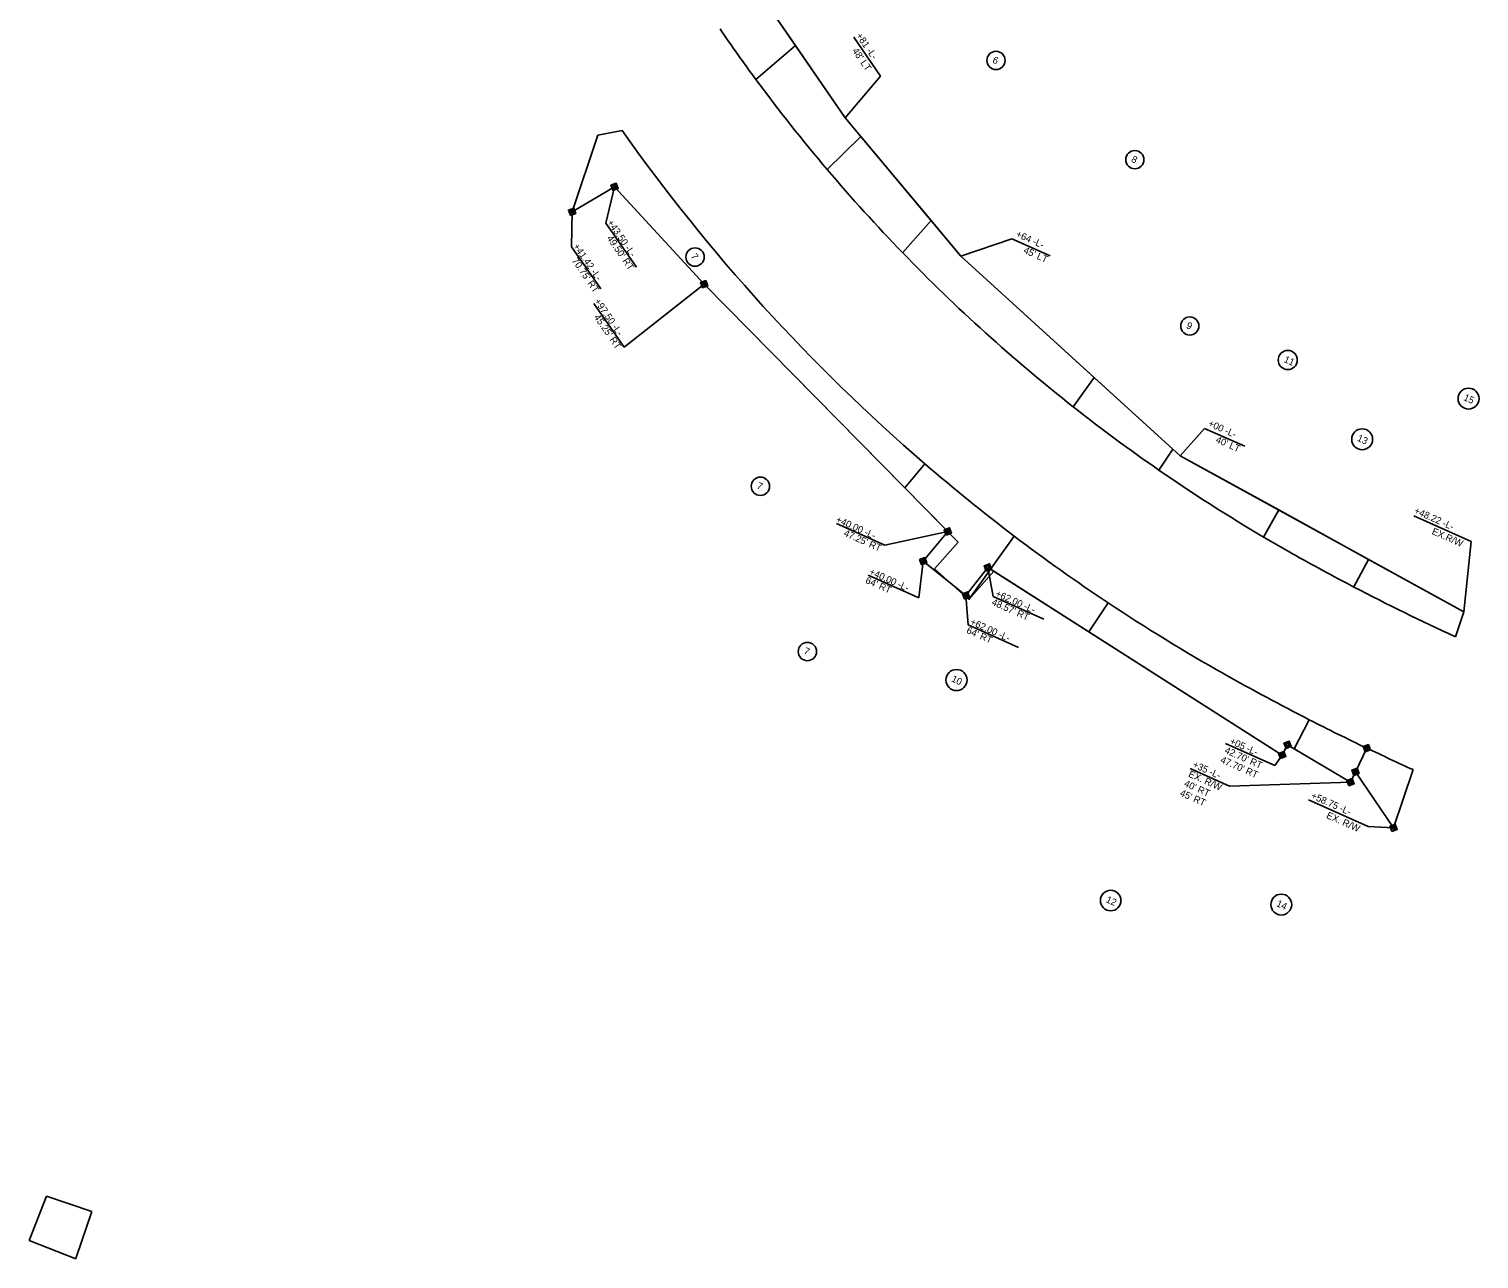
# Model space of a CAD drawing. Extents: x 2298011 to 2299093, y 599361 to 600353.
# Drawn here: x 2298011 to 2298640, y 599406 to 599940 of the extents above; entities that cross this region are included whole.
import ezdxf

# ---------------------------------------------------------------- set-up
doc = ezdxf.new("R2010")
doc.units = 0
for name, color, linetype in [('Prop Easement Construction', 7, 'Continuous'), ('Prop Easement Construction Station Offsets', 7, 'Continuous'), ('Prop Easement Permanent Drainage', 7, 'Continuous'), ('Prop Easement Permanent Drainage Station Offsets', 7, 'Continuous'), ('Prop Easement Permanent Utility', 7, 'Continuous'), ('Prop Easement Permanent Utility Station Offsets', 7, 'Continuous'), ('Prop Parcel Number Text', 7, 'Continuous'), ('Prop ROW Marker CELL', 7, 'Continuous'), ('Prop ROW Permanent Easement CELL', 7, 'Continuous'), ('Scratch_Level_2', 7, 'Continuous'), ('Scratch_Level_4', 7, 'Continuous'), ('Scratch_Level_5', 7, 'Continuous'), ('Scratch_Level_6', 7, 'Continuous')]:
    doc.layers.add(name, color=color, linetype=linetype)

msp = doc.modelspace()

# ---------------------------------------------------------------- linework, layer by layer
at = {"layer": 'Prop Easement Construction'}
for p, q in [((2298319.51, 599967.44), (2298365.22, 599901.13)), ((2298365.22, 599901.13), (2298415.34, 599841.11)), ((2298415.34, 599841.11), (2298510.52, 599754.45)), ((2298510.52, 599754.45), (2298633.57, 599686.89))]:
    msp.add_line(p, q, dxfattribs=at)
at = {"layer": 'Prop Easement Construction Station Offsets'}
for p, q in [((2298380.55, 599919.15), (2298368.88, 599936.09)), ((2298454.03, 599841.2), (2298437.51, 599848.57)), ((2298538.45, 599758.63), (2298521.09, 599766.38)), ((2298636.74, 599717.38), (2298611.76, 599728.53))]:
    msp.add_line(p, q, dxfattribs=at)
for points in [[(2298380.55, 599919.15), (2298365.22, 599901.13)], [(2298437.51, 599848.57), (2298415.34, 599841.11)], [(2298521.09, 599766.38), (2298510.52, 599754.45)], [(2298636.74, 599717.38), (2298633.57, 599686.89)]]:
    msp.add_lwpolyline(points, dxfattribs=at)
at = {"layer": 'Prop Easement Permanent Drainage'}
for q in [(2298591.42, 599627.76), (2298603.03, 599593.21)]:
    msp.add_line((2298586.49, 599617.47), q, dxfattribs=at)
at = {"layer": 'Prop Easement Permanent Drainage Station Offsets'}
for p, q in [((2298531.8, 599611.31), (2298514.83, 599618.89)), ((2298592.08, 599593.74), (2298566.18, 599605.3))]:
    msp.add_line(p, q, dxfattribs=at)
for points in [[(2298584.34, 599612.96), (2298531.8, 599611.31)], [(2298603.03, 599593.21), (2298592.08, 599593.74)]]:
    msp.add_lwpolyline(points, dxfattribs=at)
at = {"layer": 'Prop Easement Permanent Utility'}
for p, q in [((2298246.73, 599860.36), (2298265.17, 599871.14)), ((2298265.17, 599871.14), (2298303.97, 599828.92)), ((2298303.97, 599828.92), (2298409.7, 599721.74)), ((2298409.7, 599721.74), (2298399.05, 599708.83)), ((2298399.05, 599708.83), (2298417.58, 599693.96)), ((2298417.58, 599693.96), (2298427.07, 599706.13)), ((2298427.07, 599706.13), (2298554.76, 599624.77)), ((2298554.76, 599624.77), (2298557.08, 599629.2)), ((2298557.08, 599629.2), (2298584.34, 599612.96)), ((2298584.34, 599612.96), (2298586.49, 599617.47))]:
    msp.add_line(p, q, dxfattribs=at)
at = {"layer": 'Prop Easement Permanent Utility Station Offsets'}
for p, q in [((2298274.63, 599836.25), (2298261.41, 599855.45)), ((2298259.13, 599826.9), (2298246.54, 599845.19)), ((2298269.26, 599801.68), (2298256.21, 599820.62)), ((2298382.35, 599715.8), (2298361.35, 599725.17)), ((2298397.06, 599693), (2298375.14, 599702.78)), ((2298451.31, 599683.66), (2298429.39, 599693.44)), ((2298440.38, 599671.4), (2298418.46, 599681.18)), ((2298551.58, 599620.2), (2298530.09, 599629.79))]:
    msp.add_line(p, q, dxfattribs=at)
for points in [[(2298265.17, 599871.14), (2298261.41, 599855.45)], [(2298246.73, 599860.36), (2298246.54, 599845.19)], [(2298303.97, 599828.92), (2298269.26, 599801.68)], [(2298382.35, 599715.8), (2298409.7, 599721.74)], [(2298397.06, 599693), (2298399.05, 599708.83)], [(2298427.07, 599706.13), (2298429.39, 599693.44)], [(2298417.58, 599693.96), (2298418.46, 599681.18)], [(2298554.76, 599624.77), (2298551.58, 599620.2)]]:
    msp.add_lwpolyline(points, dxfattribs=at)
at = {"layer": 'Prop Parcel Number Text'}
for centre, radius in [((2298430.58, 599925.96), 3.95), ((2298490.8, 599882.94), 3.95), ((2298300.07, 599840.71), 3.98), ((2298514.64, 599810.81), 3.94), ((2298557.14, 599796.05), 4.15), ((2298635.55, 599779.31), 4.54), ((2298589.4, 599761.68), 4.53), ((2298328.43, 599741.29), 3.98), ((2298348.79, 599669.65), 3.98), ((2298413.47, 599657.29), 4.58), ((2298480.35, 599561.66), 4.46), ((2298554.33, 599559.91), 4.52)]:
    msp.add_circle(centre, radius, dxfattribs=at)
at = {"layer": 'Prop ROW Marker CELL'}
for p, q in [((2298265.17, 599871.14), (2298265.17, 599871.14)), ((2298246.73, 599860.36), (2298246.73, 599860.36)), ((2298303.97, 599828.92), (2298303.97, 599828.92)), ((2298409.7, 599721.74), (2298409.7, 599721.74)), ((2298399.05, 599708.83), (2298399.05, 599708.83)), ((2298427.07, 599706.13), (2298427.07, 599706.13)), ((2298417.58, 599693.96), (2298417.58, 599693.96)), ((2298557.08, 599629.2), (2298557.08, 599629.2)), ((2298554.76, 599624.77), (2298554.76, 599624.77)), ((2298591.42, 599627.76), (2298591.42, 599627.76)), ((2298586.49, 599617.47), (2298586.49, 599617.47)), ((2298584.34, 599612.96), (2298584.34, 599612.96)), ((2298603.03, 599593.21), (2298603.03, 599593.21))]:
    msp.add_line(p, q, dxfattribs=at)
at = {"layer": 'Prop ROW Permanent Easement CELL'}
for points in [[(2298264.47, 599869.57), (2298263.59, 599871.85), (2298265.88, 599872.72), (2298266.75, 599870.44)], [(2298264.82, 599870.35), (2298264.38, 599871.5), (2298265.52, 599871.93), (2298265.96, 599870.79)], [(2298246.02, 599858.78), (2298245.15, 599861.06), (2298247.43, 599861.94), (2298248.3, 599859.65)], [(2298246.37, 599859.57), (2298245.94, 599860.71), (2298247.08, 599861.15), (2298247.51, 599860.01)], [(2298303.27, 599827.34), (2298302.39, 599829.62), (2298304.68, 599830.5), (2298305.55, 599828.22)], [(2298303.62, 599828.13), (2298303.18, 599829.27), (2298304.32, 599829.71), (2298304.76, 599828.57)], [(2298409, 599720.16), (2298408.13, 599722.45), (2298410.41, 599723.32), (2298411.28, 599721.04)], [(2298409.35, 599720.95), (2298408.91, 599722.09), (2298410.06, 599722.53), (2298410.49, 599721.39)], [(2298398.34, 599707.25), (2298397.47, 599709.53), (2298399.75, 599710.4), (2298400.62, 599708.12)], [(2298398.69, 599708.04), (2298398.26, 599709.18), (2298399.4, 599709.61), (2298399.83, 599708.47)], [(2298426.36, 599704.55), (2298425.49, 599706.83), (2298427.77, 599707.7), (2298428.65, 599705.42)], [(2298426.72, 599705.34), (2298426.28, 599706.48), (2298427.42, 599706.91), (2298427.86, 599705.77)], [(2298416.87, 599692.38), (2298416, 599694.66), (2298418.28, 599695.54), (2298419.16, 599693.25)], [(2298417.23, 599693.17), (2298416.79, 599694.31), (2298417.93, 599694.75), (2298418.37, 599693.61)], [(2298556.38, 599627.62), (2298555.5, 599629.9), (2298557.79, 599630.77), (2298558.66, 599628.49)], [(2298556.73, 599628.41), (2298556.29, 599629.55), (2298557.43, 599629.99), (2298557.87, 599628.84)], [(2298590.71, 599626.18), (2298589.84, 599628.46), (2298592.12, 599629.33), (2298592.99, 599627.05)], [(2298554.05, 599623.19), (2298553.18, 599625.47), (2298555.46, 599626.35), (2298556.34, 599624.07)], [(2298554.41, 599623.98), (2298553.97, 599625.12), (2298555.11, 599625.56), (2298555.55, 599624.42)], [(2298591.06, 599626.97), (2298590.63, 599628.11), (2298591.77, 599628.55), (2298592.2, 599627.4)], [(2298585.79, 599615.89), (2298584.92, 599618.17), (2298587.2, 599619.04), (2298588.07, 599616.76)], [(2298586.14, 599616.68), (2298585.7, 599617.82), (2298586.85, 599618.25), (2298587.28, 599617.11)], [(2298583.63, 599611.38), (2298582.76, 599613.66), (2298585.04, 599614.53), (2298585.91, 599612.25)], [(2298583.98, 599612.17), (2298583.55, 599613.31), (2298584.69, 599613.74), (2298585.13, 599612.6)], [(2298602.33, 599591.63), (2298601.45, 599593.91), (2298603.73, 599594.79), (2298604.61, 599592.5)], [(2298602.68, 599592.42), (2298602.24, 599593.56), (2298603.38, 599594), (2298603.82, 599592.86)]]:
    msp.add_lwpolyline(points, close=True, dxfattribs=at)
at = {"layer": 'Scratch_Level_2'}
for p, q in [((2298591.42, 599627.76), (2298586.5, 599617.48)), ((2298586.5, 599617.48), (2298603.03, 599593.21)), ((2298603.03, 599593.21), (2298611.51, 599618.43)), ((2298018.76, 599433.52), (2298011.18, 599414.21)), ((2298038.38, 599426.89), (2298018.76, 599433.52)), ((2298031.7, 599406.93), (2298038.38, 599426.89)), ((2298011.18, 599414.21), (2298031.47, 599406.24)), ((2298031.47, 599406.24), (2298031.7, 599406.93))]:
    msp.add_line(p, q, dxfattribs=at)
msp.add_arc((2299031.95, 600551.04), 1023, 244.4927, 245.73365, dxfattribs=at)
at = {"layer": 'Scratch_Level_4'}
for p, q in [((2298257.83, 599893.53), (2298246.73, 599860.36)), ((2298268.41, 599895.58), (2298257.83, 599893.53)), ((2298246.73, 599860.36), (2298265.17, 599871.14)), ((2298265.17, 599871.14), (2298265.17, 599871.14)), ((2298399.69, 599751.09), (2298391.09, 599740.61)), ((2298391.09, 599740.61), (2298399.69, 599751.09)), ((2298391.09, 599740.61), (2298414.25, 599717.13)), ((2298414.25, 599717.13), (2298403.87, 599705.48)), ((2298418.8, 599692.17), (2298438.5, 599719.7)), ((2298438.5, 599719.7), (2298418.8, 599692.17)), ((2298403.87, 599705.48), (2298418.8, 599692.17)), ((2298418.8, 599692.17), (2298429.72, 599704.43)), ((2298429.72, 599704.43), (2298429.72, 599704.43)), ((2298429.72, 599704.43), (2298470.92, 599678.19)), ((2298470.92, 599678.19), (2298479.26, 599690.73)), ((2298479.26, 599690.73), (2298470.92, 599678.19)), ((2298470.92, 599678.19), (2298554.76, 599624.77)), ((2298529.29, 599660.05), (2298529.46, 599659.96)), ((2298529.46, 599659.96), (2298529.29, 599660.05)), ((2298559.93, 599627.5), (2298566.45, 599640.09)), ((2298566.45, 599640.09), (2298559.93, 599627.5)), ((2298554.76, 599624.77), (2298557.08, 599629.2)), ((2298557.08, 599629.2), (2298559.93, 599627.5)), ((2298559.93, 599627.5), (2298584.34, 599612.96)), ((2298584.34, 599612.96), (2298591.42, 599627.76))]:
    msp.add_line(p, q, dxfattribs=at)
msp.add_lwpolyline([(2298265.17, 599871.14), (2298303.97, 599828.92), (2298391.09, 599740.61)], dxfattribs=at)
for centre, radius, start, end in [((2298923.23, 600358.64), 802, 215.26644, 229.2479), ((2298923.23, 600358.64), 802, 229.2479, 232.81459), ((2298923.23, 600358.64), 802, 232.81459, 236.38722), ((2298923.23, 600358.64), 802, 236.38722, 240.58137), ((2299031.95, 600551.04), 1023, 240.58137, 242.93299), ((2299031.95, 600551.04), 1023, 242.93299, 244.4927)]:
    msp.add_arc(centre, radius, start, end, dxfattribs=at)
at = {"layer": 'Scratch_Level_5'}
for p, q in [((2298558.76, 599712.31), (2298558.93, 599712.22)), ((2298529.29, 599660.05), (2298529.46, 599659.96)), ((2298031.7, 599406.93), (2298031.47, 599406.24))]:
    msp.add_line(p, q, dxfattribs=at)
at = {"layer": 'Scratch_Level_6'}
for p, q in [((2298343.6, 599932.49), (2298319.51, 599967.44)), ((2298326.43, 599917.74), (2298343.6, 599932.49)), ((2298343.6, 599932.49), (2298326.43, 599917.74)), ((2298365.22, 599901.13), (2298343.6, 599932.49)), ((2298372.03, 599892.98), (2298365.22, 599901.13)), ((2298357.4, 599878.63), (2298372.03, 599892.98)), ((2298372.03, 599892.98), (2298357.4, 599878.63)), ((2298402.47, 599856.53), (2298372.03, 599892.98)), ((2298390.11, 599842.54), (2298402.47, 599856.53)), ((2298402.47, 599856.53), (2298390.11, 599842.54)), ((2298415.34, 599841.11), (2298402.47, 599856.53)), ((2298473.15, 599788.47), (2298415.34, 599841.11)), ((2298464.11, 599775.73), (2298473.15, 599788.47)), ((2298473.15, 599788.47), (2298464.11, 599775.73)), ((2298507.31, 599757.38), (2298473.15, 599788.47)), ((2298501.26, 599748.3), (2298507.31, 599757.38)), ((2298507.31, 599757.38), (2298501.26, 599748.3)), ((2298510.52, 599754.45), (2298507.31, 599757.38)), ((2298553.2, 599731.02), (2298510.52, 599754.45)), ((2298546.67, 599719.28), (2298553.2, 599731.02)), ((2298553.2, 599731.02), (2298546.67, 599719.28)), ((2298592.17, 599709.62), (2298553.2, 599731.02)), ((2298558.93, 599712.22), (2298558.76, 599712.31)), ((2298558.76, 599712.31), (2298558.93, 599712.22)), ((2298585.79, 599697.63), (2298592.17, 599709.62)), ((2298592.17, 599709.62), (2298585.79, 599697.63)), ((2298633.57, 599686.89), (2298592.17, 599709.62)), ((2298629.89, 599675.99), (2298633.57, 599686.89))]:
    msp.add_line(p, q, dxfattribs=at)
for centre, radius, start, end in [((2298923.23, 600358.64), 742, 214.38555, 216.456), ((2298923.23, 600358.64), 742, 216.456, 220.30909), ((2298923.23, 600358.64), 742, 220.30909, 224.07038), ((2298923.23, 600358.64), 742, 224.07038, 231.77503), ((2298923.23, 600358.64), 742, 231.77503, 235.34085), ((2298923.23, 600358.64), 742, 235.34085, 239.50361), ((2298923.23, 600358.64), 742, 239.50361, 240.58137), ((2299031.95, 600551.04), 963, 240.58137, 242.4002), ((2299031.95, 600551.04), 963, 242.4002, 245.32321)]:
    msp.add_arc(centre, radius, start, end, dxfattribs=at)

# ---------------------------------------------------------------- texts
at = {"layer": 'Prop Easement Construction Station Offsets'}
for s, rotation, p in [('+81 -L-', 304.55406, (2298369.74, 599936.68)), ("48' LT", 304.55406, (2298368.06, 599930.16)), ('+64 -L-', 335.94476, (2298438.94, 599849.63)), ("45' LT", 335.94476, (2298442.22, 599842.6)), ('+00 -L-', 335.94476, (2298522.35, 599767.51)), ("40' LT", 335.94476, (2298525.63, 599760.49)), ('+48.22 -L-', 335.94476, (2298611.65, 599729.72)), ('EX.R/W', 335.94476, (2298619.34, 599720.72))]:
    msp.add_text(s, height=3, rotation=rotation, dxfattribs=at).set_placement(p)
at = {"layer": 'Prop Easement Permanent Drainage Station Offsets'}
for s, p in [('EX. R/W', (2298513.75, 599615.48)), ('+35 -L-', (2298515.58, 599619.59)), ("40' RT", (2298511.91, 599611.37)), ("45' RT", (2298510.08, 599607.26)), ('+58.75 -L-', (2298567, 599606.08)), ('EX. R/W', (2298573.6, 599597.56))]:
    msp.add_text(s, height=3, rotation=335.94476, dxfattribs=at).set_placement(p)
at = {"layer": 'Prop Easement Permanent Utility Station Offsets'}
for s, rotation, p in [('+43.50 -L-', 304.55406, (2298261.8, 599855.64)), ("49.50' RT", 304.55406, (2298261.63, 599848.84)), ('+41.42 -L-', 304.55406, (2298247.05, 599845.33)), ("70.75' RT", 304.55406, (2298246.47, 599839.12)), ('+97.50 -L-', 304.55406, (2298256.21, 599821.45)), ("45.25' RT", 304.55406, (2298256.04, 599814.65)), ('+40.00 -L-', 335.94476, (2298360.9, 599725.84)), ("47.25' RT", 335.94476, (2298364.29, 599719.95)), ('+40.00 -L-', 335.94476, (2298375.32, 599703.17)), ("64' RT", 335.94476, (2298373.69, 599699.52)), ("48.57' RT", 335.94476, (2298428.42, 599690.04)), ('+62.00 -L-', 335.94476, (2298430.05, 599693.7)), ("64' RT", 335.94476, (2298417.49, 599677.78)), ('+62.00 -L-', 335.94476, (2298419.12, 599681.44)), ('+05 -L-', 335.94476, (2298531.72, 599629.7)), ("47.70' RT", 335.94476, (2298527.66, 599621.66)), ("42.70' RT", 335.94476, (2298529.49, 599625.77))]:
    msp.add_text(s, height=3, rotation=rotation, dxfattribs=at).set_placement(p)
at = {"layer": 'Prop Parcel Number Text'}
for s, rotation, p in [('6', 337.05704, (2298428.81, 599925.08)), ('8', 332.43128, (2298488.96, 599882.21)), ('7', 305.47669, (2298298.04, 599840.98)), ('9', 335.94476, (2298512.87, 599809.96)), ('11', 335.94476, (2298555.18, 599795.28)), ('15', 335.94476, (2298633.11, 599778.76)), ('13', 335.94476, (2298586.97, 599761.12)), ('7', 335.94476, (2298326.54, 599740.49)), ('7', 335.94476, (2298346.91, 599668.85)), ('10', 335.94476, (2298410.98, 599656.76)), ('12', 335.94476, (2298478, 599561.06)), ('14', 335.94476, (2298551.92, 599559.34))]:
    msp.add_text(s, height=3, rotation=rotation, dxfattribs=at).set_placement(p)

doc.saveas('drawing.dxf')
